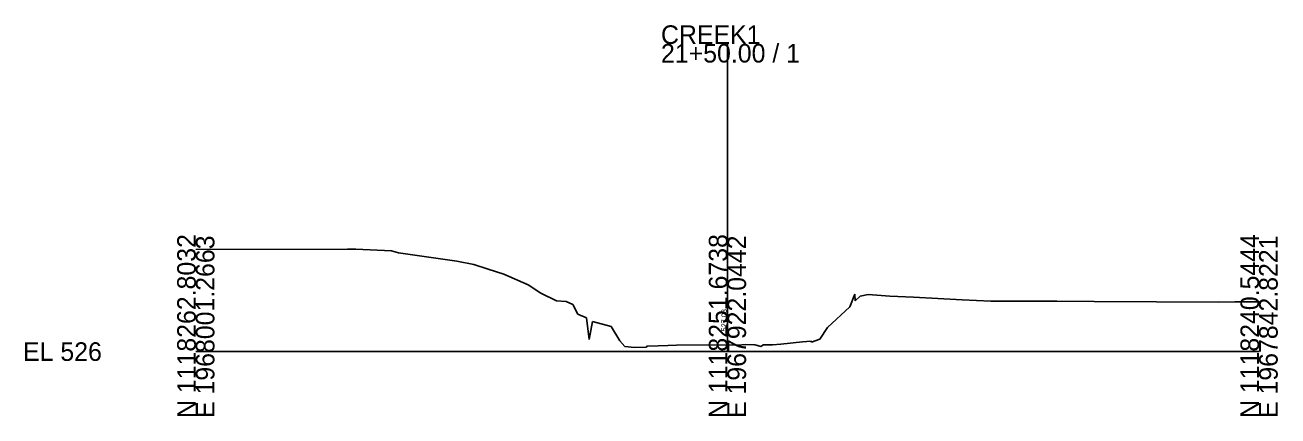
# Model space of a CAD drawing. Extents: x -26 to 163, y -10 to 10052.
# Drawn here: x -25.7 to 162.8, y 990.3 to 1049.2 of the extents above; entities that cross this region are included whole.
import ezdxf

# ---------------------------------------------------------------- set-up
doc = ezdxf.new("R2010")
doc.units = 0
for name, color, linetype in [('RD_GPK_XS_Cell', 7, 'Continuous'), ('RD_XS_ExGround', 7, 'Continuous'), ('RD_XS_TX_Elev_EX', 7, 'Continuous')]:
    doc.layers.add(name, color=color, linetype=linetype)

msp = doc.modelspace()

# ---------------------------------------------------------------- linework, layer by layer
at = {"layer": 'RD_GPK_XS_Cell'}
for p, q in [((80, 1000), (80, 1046.33)), ((0, 1000), (80, 1000)), ((80, 1000), (160, 1000))]:
    msp.add_line(p, q, dxfattribs=at)
at = {"layer": 'RD_XS_ExGround'}
for p, q in [((0, 1015.35), (22.85, 1015.44)), ((22.85, 1015.44), (24.09, 1015.44)), ((24.09, 1015.44), (29.46, 1015.17)), ((29.46, 1015.17), (30.5, 1014.87)), ((30.5, 1014.87), (39.3, 1013.64)), ((39.3, 1013.64), (41.82, 1013.1)), ((41.82, 1013.1), (44.01, 1012.43)), ((44.01, 1012.43), (46.34, 1011.67)), ((46.34, 1011.67), (50.01, 1010.05)), ((50.01, 1010.05), (51.9, 1008.79)), ((51.9, 1008.79), (54.27, 1007.64)), ((98.4, 1006.73), (99.17, 1008.66)), ((99.17, 1008.66), (99.24, 1007.64)), ((54.27, 1007.64), (55.73, 1007.52)), ((55.73, 1007.52), (56.75, 1007.08)), ((56.75, 1007.08), (57.47, 1005.65)), ((99.24, 1007.64), (99.95, 1008.34)), ((99.95, 1008.34), (101.19, 1008.6)), ((101.19, 1008.6), (104.44, 1008.33)), ((104.44, 1008.33), (107.99, 1008.18)), ((107.99, 1008.18), (115.32, 1007.8)), ((115.32, 1007.8), (119.62, 1007.58)), ((119.62, 1007.58), (129.57, 1007.59)), ((129.57, 1007.59), (135.17, 1007.56)), ((135.17, 1007.56), (153.93, 1007.46)), ((153.93, 1007.46), (156.33, 1007.48)), ((156.33, 1007.48), (160, 1007.51)), ((57.47, 1005.65), (58.81, 1005.06)), ((58.81, 1005.06), (59.21, 1001.84)), ((95.05, 1003.65), (98.4, 1006.73)), ((59.21, 1001.84), (59.71, 1004.53)), ((59.71, 1004.53), (62.5, 1003.8)), ((62.5, 1003.8), (63.83, 1001.63)), ((93.9, 1001.86), (95.05, 1003.65)), ((63.83, 1001.63), (64.58, 1000.75)), ((86.78, 1001.04), (88.05, 1001.14)), ((88.05, 1001.14), (91.32, 1001.48)), ((91.32, 1001.48), (92.61, 1001.57)), ((92.61, 1001.57), (92.63, 1001.4)), ((92.63, 1001.4), (93.9, 1001.86)), ((64.58, 1000.75), (66.02, 1000.63)), ((66.02, 1000.63), (67.81, 1000.68)), ((67.81, 1000.68), (67.87, 1000.8)), ((67.87, 1000.8), (69.57, 1000.86)), ((69.57, 1000.86), (71.01, 1000.9)), ((71.01, 1000.9), (72.36, 1000.98)), ((72.36, 1000.98), (80, 1001.03)), ((80, 1001.03), (81.52, 1000.98)), ((81.52, 1000.98), (82.77, 1001.08)), ((82.77, 1001.08), (84.12, 1001.04)), ((84.12, 1001.04), (85.08, 1000.75)), ((85.08, 1000.75), (85.39, 1001.01)), ((85.39, 1001.01), (86.78, 1001.04))]:
    msp.add_line(p, q, dxfattribs=at)

# ---------------------------------------------------------------- texts
at = {"layer": 'RD_GPK_XS_Cell'}
for s, p in [('CREEK1', (70, 1046.33)), ('21+50.00 / 1', (70, 1043.53)), ('EL 526', (-26, 998.6))]:
    msp.add_text(s, height=2.8, dxfattribs=at).set_placement(p)
for s, p in [('N 1118262.8032', (0, 990)), ('E 1968001.2663', (2.8, 990)), ('N 1118251.6738', (80, 990)), ('E 1967922.0442', (82.8, 990)), ('N 1118240.5444', (160, 990)), ('E 1967842.8221', (162.8, 990))]:
    msp.add_text(s, height=2.8, rotation=90, dxfattribs=at).set_placement(p)
at = {"layer": 'RD_XS_TX_Elev_EX'}
msp.add_text('527.03', height=0.8, rotation=90, dxfattribs=at).set_placement((79.9, 1003.03))

doc.saveas('drawing.dxf')
